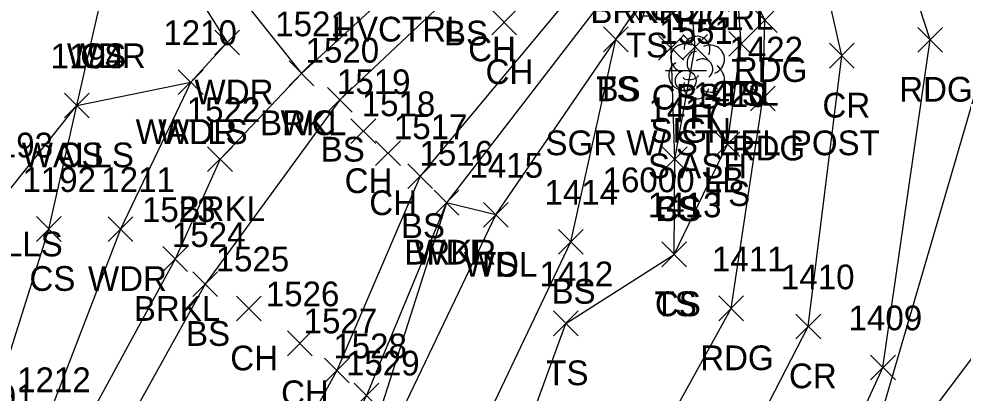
# Model space of a CAD drawing. Extents: x 1441651 to 1442140, y 243798 to 245625.
# Drawn here: x 1441999.2 to 1442075.5, y 245354.1 to 245384.4 of the extents above; entities that cross this region are included whole.
import ezdxf

# ---------------------------------------------------------------- set-up
doc = ezdxf.new("R2010")
doc.units = 0
for name, color, linetype in [('B_A', 7, 'Continuous'), ('C_A', 7, 'Continuous'), ('L_A', 7, 'Continuous'), ('L_C', 7, 'Continuous'), ('L_I', 7, 'Continuous'), ('L_TIC', 7, 'Continuous'), ('LAWA', 7, 'Continuous'), ('LAWE', 7, 'Continuous'), ('LELB', 7, 'Continuous'), ('LTD', 7, 'Continuous'), ('LWS', 7, 'Continuous'), ('P_A', 7, 'Continuous'), ('P_I', 7, 'Continuous'), ('P_TIC', 7, 'Continuous'), ('PEU', 7, 'Continuous'), ('PRC', 7, 'Continuous'), ('R_A', 7, 'Continuous'), ('R_C', 7, 'Continuous'), ('R_TIC', 7, 'Continuous'), ('RGR', 7, 'Continuous'), ('S_A', 7, 'Continuous'), ('S_C', 7, 'Continuous'), ('S_I', 7, 'Continuous'), ('SSGN', 7, 'Continuous')]:
    doc.layers.add(name, color=color, linetype=linetype)

msp = doc.modelspace()

# ---------------------------------------------------------------- linework, layer by layer
at = {"layer": 'L_TIC'}
for points in [[(1442037.424, 245383.087), (1442039.424, 245385.087)], [(1442039.424, 245383.087), (1442037.424, 245385.087)], [(1442015.012, 245381.455), (1442017.012, 245383.455)], [(1442017.012, 245381.455), (1442015.012, 245383.455)], [(1442046.447, 245381.708), (1442048.447, 245383.708)], [(1442048.447, 245381.708), (1442046.447, 245383.708)], [(1442046.447, 245381.708), (1442048.447, 245383.708)], [(1442048.447, 245381.708), (1442046.447, 245383.708)], [(1442056.592, 245381.339), (1442058.592, 245383.339)], [(1442058.592, 245381.339), (1442056.592, 245383.339)], [(1442050.913, 245381.032), (1442052.913, 245383.032)], [(1442052.913, 245381.032), (1442050.913, 245383.032)], [(1442052.865, 245381.108), (1442054.865, 245383.108)], [(1442054.865, 245381.108), (1442052.865, 245383.108)], [(1442021.028, 245378.959), (1442023.028, 245380.959)], [(1442023.028, 245378.959), (1442021.028, 245380.959)], [(1442021.028, 245378.959), (1442023.028, 245380.959)], [(1442023.028, 245378.959), (1442021.028, 245380.959)], [(1442012.066, 245378.249), (1442014.066, 245380.249)], [(1442014.066, 245378.249), (1442012.066, 245380.249)], [(1442012.066, 245378.249), (1442014.066, 245380.249)], [(1442014.066, 245378.249), (1442012.066, 245380.249)], [(1442024.138, 245376.826), (1442026.138, 245378.826)], [(1442026.138, 245376.826), (1442024.138, 245378.826)], [(1442002.863, 245376.365), (1442004.863, 245378.365)], [(1442004.863, 245376.365), (1442002.863, 245378.365)], [(1442002.863, 245376.365), (1442004.863, 245378.365)], [(1442004.863, 245376.365), (1442002.863, 245378.365)], [(1442026.028, 245374.278), (1442028.028, 245376.278)], [(1442028.028, 245374.278), (1442026.028, 245376.278)], [(1442055.489, 245373.235), (1442057.489, 245375.235)], [(1442057.489, 245373.235), (1442055.489, 245375.235)], [(1442014.438, 245372.014), (1442016.438, 245374.014)], [(1442016.438, 245372.014), (1442014.438, 245374.014)], [(1442028.022, 245372.495), (1442030.022, 245374.495)], [(1442030.022, 245372.495), (1442028.022, 245374.495)], [(1442051.21, 245372.013), (1442053.21, 245374.013)], [(1442053.21, 245372.013), (1442051.21, 245374.013)], [(1442051.21, 245372.013), (1442053.21, 245374.013)], [(1442053.21, 245372.013), (1442051.21, 245374.013)], [(1442030.625, 245370.637), (1442032.625, 245372.637)], [(1442032.625, 245370.637), (1442030.625, 245372.637)], [(1442032.753, 245368.5), (1442034.753, 245370.5)], [(1442034.753, 245368.5), (1442032.753, 245370.5)], [(1442032.753, 245368.5), (1442034.753, 245370.5)], [(1442034.753, 245368.5), (1442032.753, 245370.5)], [(1442036.743, 245367.514), (1442038.743, 245369.514)], [(1442038.743, 245367.514), (1442036.743, 245369.514)], [(1442036.743, 245367.514), (1442038.743, 245369.514)], [(1442038.743, 245367.514), (1442036.743, 245369.514)], [(1442000.584, 245366.37), (1442002.584, 245368.37)], [(1442002.584, 245366.37), (1442000.584, 245368.37)], [(1442006.394, 245366.363), (1442008.394, 245368.363)], [(1442008.394, 245366.363), (1442006.394, 245368.363)], [(1442042.806, 245365.333), (1442044.806, 245367.333)], [(1442044.806, 245365.333), (1442042.806, 245367.333)], [(1442042.806, 245365.333), (1442044.806, 245367.333)], [(1442044.806, 245365.333), (1442042.806, 245367.333)], [(1442010.82, 245363.946), (1442012.82, 245365.946)], [(1442012.82, 245363.946), (1442010.82, 245365.946)], [(1442051.17, 245364.322), (1442053.17, 245366.322)], [(1442053.17, 245364.322), (1442051.17, 245366.322)], [(1442051.17, 245364.322), (1442053.17, 245366.322)], [(1442053.17, 245364.322), (1442051.17, 245366.322)], [(1442013.243, 245361.921), (1442015.243, 245363.921)], [(1442015.243, 245361.921), (1442013.243, 245363.921)], [(1442016.778, 245359.94), (1442018.778, 245361.94)], [(1442018.778, 245359.94), (1442016.778, 245361.94)], [(1442042.414, 245358.742), (1442044.414, 245360.742)], [(1442044.414, 245358.742), (1442042.414, 245360.742)], [(1442020.888, 245357.125), (1442022.888, 245359.125)], [(1442022.888, 245357.125), (1442020.888, 245359.125)], [(1442023.894, 245354.937), (1442025.894, 245356.937)], [(1442025.894, 245354.937), (1442023.894, 245356.937)], [(1442026.295, 245352.918), (1442028.295, 245354.918)], [(1442028.295, 245352.918), (1442026.295, 245354.918)]]:
    msp.add_lwpolyline(points, dxfattribs=at)
at = {"layer": 'LAWA'}
for points in [[(1441938.824, 245423.156), (1441966.589, 245419.586), (1441980.426, 245407.309), (1441994.994, 245393.975), (1442005.692, 245385.381), (1442010.091, 245391.874), (1442016.012, 245382.455), (1442013.066, 245379.249), (1442007.394, 245367.363), (1442001.156, 245351.178), (1441996.637, 245344.411), (1441988.517, 245326.607)], [(1442003.622, 245279.784), (1442006.134, 245298.923), (1442019.239, 245330.198), (1442028.145, 245348.476), (1442037.743, 245368.514), (1442033.753, 245369.5), (1442028.331, 245352.526), (1442017.833, 245331.971), (1442010.377, 245316.92), (1442001.664, 245295.024)]]:
    msp.add_lwpolyline(points, dxfattribs=at)
at = {"layer": 'LAWE'}
for points in [[(1441907.704, 245568.198), (1441910.354, 245545.097), (1441926.401, 245522.195), (1441938.487, 245498.109), (1441943.431, 245489.962), (1441943.382, 245477.871), (1441945.819, 245463.28), (1441949.518, 245451.716), (1441958.04, 245451.396), (1441967.21, 245432.067), (1441993.811, 245408.343), (1442003.996, 245402.527), (1442022.028, 245379.959)], [(1442099.331, 245492.7), (1442082.175, 245474.825), (1442073.962, 245459.556), (1442071.044, 245454.669), (1442067.5, 245447.08), (1442064.769, 245439.016), (1442060.82, 245433.995), (1442057.711, 245424.573), (1442056.016, 245422.421), (1442050.947, 245416.77), (1442046.422, 245406.149), (1442038.474, 245397.39), (1442032.995, 245390.022), (1442022.028, 245379.959), (1442015.438, 245373.014), (1442011.82, 245364.946), (1441999.311, 245341.928), (1441993.277, 245326.588), (1441983.696, 245301.797)], [(1442108.799, 245476.467), (1442096.827, 245461.697), (1442085.936, 245448.636), (1442079.446, 245435.792), (1442078.126, 245432.436), (1442074.215, 245419.929), (1442069.905, 245412.33), (1442066.174, 245406.441), (1442060.085, 245400.813), (1442053.875, 245394.968), (1442048.801, 245389.024), (1442033.753, 245369.5), (1442027.295, 245353.918), (1442016.143, 245332.931), (1442008.363, 245317.18), (1442000.261, 245295.499)]]:
    msp.add_lwpolyline(points, dxfattribs=at)
at = {"layer": 'LELB'}
for points in [[(1442102.458, 245487.565), (1442084.345, 245473.245), (1442077.162, 245458.74), (1442072.716, 245452.8), (1442069.733, 245445.651), (1442066.867, 245437.139), (1442063.415, 245431.599), (1442060.353, 245422.411), (1442058.711, 245418.726), (1442054.414, 245414.049), (1442047.261, 245402.979), (1442041.756, 245394.877), (1442035.105, 245387.217), (1442025.138, 245377.826), (1442014.243, 245362.921), (1442001.678, 245340.269), (1441995.167, 245325.255), (1441985.519, 245301.167)], [(1442107.479, 245478.045), (1442095.111, 245463.136), (1442085.124, 245450.231), (1442079.931, 245439.38), (1442074.016, 245430.6), (1442072.192, 245422.421), (1442067.602, 245415.77), (1442063.525, 245410.875), (1442058.938, 245403.451), (1442051.468, 245396.66), (1442047.361, 245390.552), (1442031.625, 245371.637), (1442024.894, 245355.937), (1442013.328, 245334.791), (1442005.478, 245318.663), (1441997.832, 245296.612)], [(1442128.7, 245453.168), (1442114.47, 245439.461), (1442106.293, 245436.041), (1442091.133, 245416.249), (1442087.362, 245410.975), (1442078.918, 245407.703), (1442072.375, 245401.791), (1442078.662, 245393.315), (1442088.165, 245379.007), (1442078.347, 245359.722), (1442066.466, 245343.929), (1442051.618, 245313.899)], [(1441955.268, 245346.863), (1441965.214, 245362.626), (1441976.129, 245373.643), (1441994.994, 245393.975), (1441992.503, 245375.663), (1441988.382, 245359.287), (1441985.514, 245329.274), (1441996.05, 245349.813), (1442001.584, 245367.37), (1442003.863, 245377.365), (1442005.692, 245385.381), (1442010.091, 245391.874)], [(1442066.466, 245343.929), (1442078.106, 245383.773), (1442072.276, 245394.261)], [(1442052.21, 245373.013), (1442053.865, 245382.108), (1442053.071, 245391.658)], [(1442052.17, 245365.322), (1442052.21, 245373.013), (1442051.913, 245382.032), (1442051.717, 245389.254)], [(1442037.743, 245368.514), (1442047.447, 245382.708), (1442049.85, 245386.244)], [(1442043.806, 245366.333), (1442047.447, 245382.708)], [(1442018.783, 245272.122), (1442018.727, 245299.129), (1442032.619, 245323.339), (1442037.764, 245344.274), (1442043.414, 245359.742), (1442052.17, 245365.322), (1442056.489, 245374.235), (1442057.592, 245382.339)], [(1442015.719, 245274.915), (1442013.146, 245299.508), (1442027.616, 245327.16), (1442034.196, 245346.114), (1442043.806, 245366.333)]]:
    msp.add_lwpolyline(points, dxfattribs=at)
at = {"layer": 'LTD'}
msp.add_line((1442053.967, 245380.476), (1442053.967, 245380.476), dxfattribs=at)
msp.add_line((1442053.967, 245380.476), (1442053.967, 245380.476), dxfattribs=at)
msp.add_arc((1442054.014, 245381.91), 1.047, 335.52715, 180.95627, dxfattribs=at)
for centre, major_axis, ratio, start_param, end_param in [((1442053.175, 245381.143), (1.21, -0.512), 0.895232, 1.570796, 4.712389), ((1442055.009, 245381.06), (-1.141, -0.483), 0.949671, 1.570796, 4.712389), ((1442053.759, 245380.934), (-0.208, -0.792), 0.645439, 3.141593, 6.283185), ((1442054.467, 245380.309), (-0.5, 0.667), 0.989748, 3.141593, 6.283185), ((1442052.884, 245379.768), (0.584, -1.042), 0.959034, 3.141593, 6.283185), ((1442054.967, 245379.643), (-1.09, 0.792), 0.841452, 1.570796, 4.712389), ((1442053.509, 245379.726), (-0.625, -0.083), 0.423636, 0, 3.141593), ((1442053.967, 245378.976), (0.265, 1.061), 0.942809, 1.570796, 4.712389)]:
    msp.add_ellipse(centre, major_axis=major_axis, ratio=ratio, start_param=start_param, end_param=end_param, dxfattribs=at)
at = {"layer": 'LWS'}
msp.add_lwpolyline([(1441985.514, 245329.274), (1441991.348, 245348.995), (1441998.107, 245370.164), (1442003.863, 245377.365), (1442013.066, 245379.249)], dxfattribs=at)
at = {"layer": 'P_TIC'}
for points in [[(1442058.506, 245383.265), (1442060.506, 245385.265)], [(1442060.506, 245383.265), (1442058.506, 245385.265)], [(1442071.881, 245381.672), (1442073.881, 245383.672)], [(1442073.881, 245381.672), (1442071.881, 245383.672)], [(1442064.727, 245380.387), (1442066.727, 245382.387)], [(1442066.727, 245380.387), (1442064.727, 245382.387)], [(1442058.331, 245376.916), (1442060.331, 245378.916)], [(1442060.331, 245376.916), (1442058.331, 245378.916)], [(1442055.785, 245359.956), (1442057.785, 245361.956)], [(1442057.785, 245359.956), (1442055.785, 245361.956)], [(1442062.019, 245358.496), (1442064.019, 245360.496)], [(1442064.019, 245358.496), (1442062.019, 245360.496)], [(1442068.056, 245355.182), (1442070.056, 245357.182)], [(1442070.056, 245355.182), (1442068.056, 245357.182)]]:
    msp.add_lwpolyline(points, dxfattribs=at)
at = {"layer": 'PEU'}
for points in [[(1442021.575, 245270.007), (1442029.759, 245297.223), (1442038.899, 245320.233), (1442046.726, 245342.734), (1442056.785, 245360.956), (1442059.331, 245377.916), (1442059.506, 245384.265), (1442055.546, 245392.581), (1442060.308, 245397.749), (1442066.076, 245403.514)], [(1442035.638, 245264.666), (1442045.154, 245291.534), (1442051.618, 245313.899), (1442059.292, 245334.8), (1442069.056, 245356.182), (1442072.881, 245382.672), (1442066.076, 245403.514)]]:
    msp.add_lwpolyline(points, dxfattribs=at)
at = {"layer": 'PRC'}
msp.add_lwpolyline([(1442028.667, 245266.9), (1442037.624, 245294.471), (1442044.859, 245317.347), (1442051.821, 245337.799), (1442063.019, 245359.496), (1442065.727, 245381.387), (1442063.407, 245391.635), (1442060.308, 245397.749)], dxfattribs=at)
at = {"layer": 'R_TIC'}
for points in [[(1442056.592, 245381.339), (1442058.592, 245383.339)], [(1442058.592, 245381.339), (1442056.592, 245383.339)]]:
    msp.add_lwpolyline(points, dxfattribs=at)
at = {"layer": 'RGR'}
msp.add_lwpolyline([(1442057.592, 245382.339), (1442057.162, 245388.485), (1442055.546, 245392.581)], dxfattribs=at)
at = {"layer": 'SSGN'}
for p, q in [((1442051.456, 245380.199), (1442054.789, 245380.199)), ((1442053.103, 245379.366), (1442053.103, 245379.366))]:
    msp.add_line(p, q, dxfattribs=at)
msp.add_circle((1442053.103, 245379.366), 0.833, dxfattribs=at)

# ---------------------------------------------------------------- texts
at = {"layer": 'B_A'}
msp.add_text('XAT', height=1, dxfattribs=at).set_placement((1442048.554, 245384.244))
at = {"layer": 'C_A'}
msp.add_text('HVCTRL', height=2, dxfattribs=at).set_placement((1442024.503, 245382.534))
at = {"layer": 'L_A'}
for s, p in [('CS', (1442050.158, 245384.254)), ('BRKR', (1442045.392, 245384.024)), ('BS', (1442033.546, 245382.217)), ('TS', (1442048.259, 245381.244)), ('CS', (1442004.133, 245380.381)), ('CH', (1442035.508, 245380.934)), ('WDR', (1442003.054, 245380.381)), ('CH', (1442036.912, 245379.087)), ('WDR', (1442013.374, 245377.455)), ('TS', (1442045.857, 245377.708)), ('BS', (1442045.888, 245377.708)), ('TS', (1442056.002, 245377.339)), ('CS', (1442050.354, 245377.032)), ('BS', (1442052.306, 245377.108)), ('H', (1442053.4, 245375.476)), ('BRKL', (1442018.673, 245374.959)), ('WC', (1442020.335, 245374.959)), ('WALLS', (1442008.609, 245374.249)), ('WDR', (1442010.428, 245374.249)), ('BS', (1442023.579, 245372.826)), ('WALLS', (1441999.407, 245372.365)), ('CS', (1442002.304, 245372.365)), ('CH', (1442025.516, 245370.278)), ('TS', (1442054.898, 245369.235)), ('CH', (1442027.51, 245368.495)), ('BRKL', (1442012.084, 245368.014)), ('CS', (1442050.651, 245368.013)), ('BS', (1442050.651, 245368.013)), ('BS', (1442030.066, 245366.637)), ('WALLS', (1441993.65, 245365.164)), ('BRKR', (1442030.344, 245364.5)), ('WDL', (1442031.171, 245364.5)), ('WDL', (1442035.16, 245363.514)), ('TS', (1442036.152, 245363.514)), ('CS', (1442000.025, 245362.37)), ('WDR', (1442004.757, 245362.363)), ('BS', (1442042.246, 245361.333)), ('BS', (1442042.246, 245361.333)), ('BRKL', (1442008.466, 245359.946)), ('TS', (1442050.58, 245360.322)), ('CS', (1442050.611, 245360.322)), ('BS', (1442012.684, 245357.921)), ('CH', (1442016.266, 245355.94)), ('TS', (1442041.824, 245354.742)), ('CH', (1442020.377, 245353.125))]:
    msp.add_text(s, height=2, dxfattribs=at).set_placement(p)
at = {"layer": 'L_C'}
msp.add_text('S.ASH', height=2, dxfattribs=at).set_placement((1442050.046, 245371.476))
at = {"layer": 'L_I'}
for s, p in [('1421', (1442051.841, 245383.476)), ('1521', (1442019.902, 245382.959)), ('1521', (1442019.902, 245382.959)), ('1210', (1442010.853, 245382.249)), ('1210', (1442010.853, 245382.249)), ('1520', (1442022.359, 245380.826)), ('1194', (1442001.737, 245380.365)), ('1194', (1442001.737, 245380.365)), ('1519', (1442024.894, 245378.278)), ('1420', (1442053.709, 245377.235)), ('1522', (1442012.745, 245376.014)), ('1518', (1442026.896, 245376.495)), ('1417', (1442050.084, 245376.013)), ('1417', (1442050.084, 245376.013)), ('1517', (1442029.499, 245374.637)), ('1193', (1441995.981, 245373.164)), ('1516', (1442031.572, 245372.5)), ('1516', (1442031.572, 245372.5)), ('1415', (1442035.617, 245371.514)), ('1415', (1442035.617, 245371.514)), ('1192', (1441999.458, 245370.37)), ('1211', (1442005.835, 245370.363)), ('1414', (1442041.68, 245369.333)), ('1414', (1442041.68, 245369.333)), ('1413', (1442050.044, 245368.322)), ('1413', (1442050.044, 245368.322)), ('1523', (1442009.127, 245367.946)), ('1524', (1442011.55, 245365.921)), ('1525', (1442015.085, 245363.94)), ('1412', (1442041.288, 245362.742)), ('1526', (1442019.14, 245361.125)), ('1527', (1442022.201, 245358.937)), ('1528', (1442024.602, 245356.918)), ('1529', (1442025.63, 245355.526)), ('1212', (1441999.03, 245354.178)), ('1191', (1441994.491, 245352.813))]:
    msp.add_text(s, height=2, dxfattribs=at).set_placement(p)
at = {"layer": 'P_A'}
for s, p in [('RDG', (1442056.994, 245379.265)), ('RDG', (1442070.369, 245377.672)), ('CR', (1442064.16, 245376.387)), ('RDG', (1442056.819, 245372.916)), ('RDG', (1442054.273, 245355.956)), ('CR', (1442061.452, 245354.496))]:
    msp.add_text(s, height=2, dxfattribs=at).set_placement(p)
at = {"layer": 'P_I'}
for s, p in [('1422', (1442056.638, 245380.916)), ('1411', (1442055.226, 245363.956)), ('1410', (1442060.806, 245362.496)), ('1409', (1442066.277, 245359.182))]:
    msp.add_text(s, height=2, dxfattribs=at).set_placement(p)
at = {"layer": 'R_A'}
for p in [(1442054.705, 245383.485), (1442055.136, 245377.339)]:
    msp.add_text('GRL', height=2, dxfattribs=at).set_placement(p)
at = {"layer": 'R_C'}
msp.add_text('SGR W/ STEEL POST', height=2, dxfattribs=at).set_placement((1442041.758, 245373.339))
at = {"layer": 'S_A'}
msp.add_text('SIGN', height=2, dxfattribs=at).set_placement((1442050.241, 245374.346))
at = {"layer": 'S_C'}
msp.add_text('16000 LB', height=2, dxfattribs=at).set_placement((1442046.382, 245370.346))
at = {"layer": 'S_I'}
msp.add_text('1551', height=2, dxfattribs=at).set_placement((1442050.957, 245382.346))

doc.saveas('drawing.dxf')
